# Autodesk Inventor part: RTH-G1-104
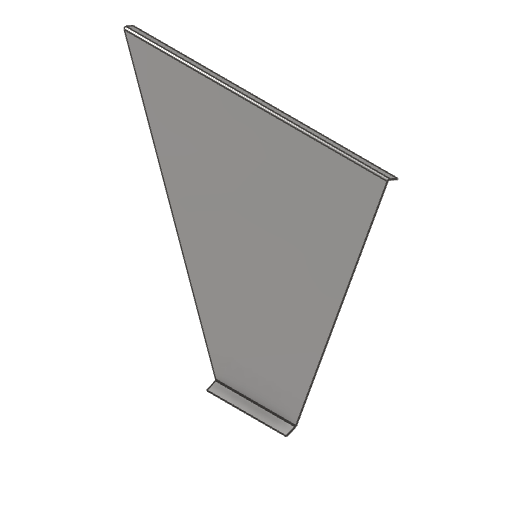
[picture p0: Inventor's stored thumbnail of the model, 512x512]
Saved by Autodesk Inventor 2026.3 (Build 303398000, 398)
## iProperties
Created: 2026-09
Part Number: RTH-G1-104
Material: Steel, Mild
Document SubType Name: Sheet Metal
Designer: mykol
Density: 7.85 g/cm^3
Sheet Metal Rule: Default_mm
Appearance: Semi-Polished
Project: RTH-G1
Description: PANEL X+ 3 CS FORMED FLANGES
Stock Number: PL 3 x 1000 x 1060
Mass: 16058.3 g
Surface Area: 13743.4 cm^2
Volume: 2045.64 cm^3
Flat Pattern Width: 96.4808 cm
Flat Pattern Length: 120.911 cm
Flat Pattern Area: 11665.6 cm^2
Sheet Metal Width: 964.808 mm
Sheet Metal Length: 1209.106 mm
Sheet Metal Area: 1166555.328 mm^2
RuthenClass: Fabricated
Thickness: 3
RuthenConfigId: RTH-G1-A-b1a1fe2e
RuthenRuleSet: 1.0.0
RuthenAddInVersion: 1.0.0
Author: mykol
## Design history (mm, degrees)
node "Face1"
  sketch "Sketch1"
    geometry: L1 (-150, 0)-(150, 0); L2 (150, 0)-(500, 984.886); L3 (500, 984.886)-(-500, 984.886); L4 (-500, 984.886)-(-150, 0)
    constraints: 8 end point
node "Flange1"
node "Flange2"
body "Solid1"
face "Plate1" dims "d0" = 3 (= Thickness)
sketch "Sketch2"
  geometry: L1 through (500, 0) direction (-1, 0); L2 through (0, -20) direction (0, -1); L3 (0, -40)-(1000, -40); L4 (1000, -40)-(1000, 0)
  constraints: 6 end point, 1 horizontal, 1 perpendicular, 1 vertical
face "Plate2" dims "d0" = 3 (= Thickness), "d1" = 3 (= Thickness), "d2" = 1.5 (= 0.5 x Thickness), "d3" = 6 (= 2 x Thickness), "d4" = 3 (= Thickness), "d5" = 40, "d6" = 19.89021, "d7" = 3 (= Thickness), "d8" = 12 (= 4 x Thickness), "d9" = 0.5, "d10" = 3 (= JacobiRadiusSize), "SeamGap" = 0.01
bend "Bend1" dims "d0" = 3 (= Thickness), "d1" = 3 (= Thickness), "d2" = 1.5 (= 0.5 x Thickness), "d3" = 6 (= 2 x Thickness), "d4" = 3 (= Thickness), "d5" = 40, "d6" = 19.89021, "d7" = 3 (= Thickness), "SeamGap" = 0.01
feature "Corner1" dims "d5" = 40, "d6" = 19.89021, "d8" = 12 (= 4 x Thickness), "d9" = 0.5, "d10" = 3 (= JacobiRadiusSize)
sketch "Sketch3"
  geometry: L1 through (-150, 0) direction (1, 0); L2 through (0, 20) direction (0, 1); L3 (0, 40)-(-300, 40); L4 (-300, 40)-(-300, 0)
  constraints: 6 end point, 1 horizontal, 1 perpendicular, 1 vertical
face "Plate3" dims "d0" = 3 (= Thickness), "d11" = 3 (= Thickness), "d12" = 1.5 (= 0.5 x Thickness), "d13" = 6 (= 2 x Thickness), "d14" = 3 (= Thickness), "d15" = 40, "d16" = 11.52572, "d17" = 3 (= Thickness), "d18" = 12 (= 4 x Thickness), "d19" = 0.5, "d20" = 3 (= JacobiRadiusSize), "SeamGap" = 0.01
bend "Bend2" dims "d0" = 3 (= Thickness), "d11" = 3 (= Thickness), "d12" = 1.5 (= 0.5 x Thickness), "d13" = 6 (= 2 x Thickness), "d14" = 3 (= Thickness), "d15" = 40, "d16" = 11.52572, "d17" = 3 (= Thickness), "SeamGap" = 0.01
feature "Corner2" dims "d15" = 40, "d16" = 11.52572, "d18" = 12 (= 4 x Thickness), "d19" = 0.5, "d20" = 3 (= JacobiRadiusSize)
feature "Definition1"
other parameters: "Thickness" = 3, "BendRadius" = 3 (= Thickness), "BendReliefWidth" = 3 (= Thickness), "BendReliefDepth" = 1.5 (= 0.5 x Thickness), "CornerReliefSize" = 12 (= 4 x Thickness), "MinimumRemnant" = 6 (= 2 x Thickness), "TransitionRadius" = 3 (= BendRadius), "JacobiRadiusSize" = 3 (= BendRadius), "GapSize" = 3 (= Thickness), "BendRadius" = 3, "BendReliefDepth" = 1.5, "BendReliefWidth" = 3, "CornerReliefSize" = 12, "GapSize" = 3, "JacobiRadiusSize" = 3, "MinimumRemnant" = 6, "Thickness" = 3, "TransitionRadius" = 3
